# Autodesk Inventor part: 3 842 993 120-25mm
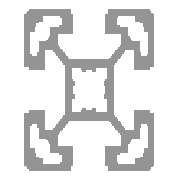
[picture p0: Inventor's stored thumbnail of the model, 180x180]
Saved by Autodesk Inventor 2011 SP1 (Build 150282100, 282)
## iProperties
Category: End -/-
Created: 2011-02
Part Number: 3 842 993 120-25mm
Document SubType Name: Modeling
Designer: SRW
Density: 2.71 g/cm^3
Categories: <MemberInstance><Categories><Category DisplayName="Structural Shapes" InternalName="089c4875-fa83-4c05-b084-43b9cc11f5ed" Mnemonic="GRDR"><CategoryParameter Dis
Stock Number: 3 842 993 120
Description: PROFILE 40x40, -/-
Material: Aluminum-6061
Mass: 37.6546 g
Surface Area: 139.763 cm^2
Volume: 13.8947 cm^3
G_L: 25.000 mm
Author: SRW
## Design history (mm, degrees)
node "Blocks"
  sketch "40x40"
    geometry: L1 (43.982, 25.257)-(43.982, 22.155); L2 (43.982, 22.155)-(47.084, 22.155); L3 (47.084, 22.155)-(47.484, 23.071); L4 (51.48, 23.071)-(51.88, 22.155); L5 (51.88, 22.155)-(54.982, 22.155); L6 (54.982, 22.155)-(54.982, 25.257); L7 (54.982, 25.257)-(54.065, 25.656); L8 (54.065, 29.653)-(54.982, 30.053); L9 (54.982, 30.053)-(54.982, 33.155); L10 (54.982, 33.155)-(51.88, 33.155); L11 (51.88, 33.155)-(51.48, 32.238); L12 (47.484, 32.238)-(47.084, 33.155); L13 (67.982, 42.155)-(66.732, 42.155); L14 (63.982, 44.905)-(63.982, 46.155); L15 (63.982, 46.155)-(58.982, 46.155); L16 (58.982, 43.155)-(61.232, 43.155); L17 (61.232, 43.155)-(61.232, 42.155); L18 (63.982, 39.405)-(64.982, 39.405); L19 (64.982, 39.405)-(64.982, 37.155); L20 (67.982, 37.155)-(67.982, 42.155); L21 (54.482, 9.155)-(55.282, 9.155); L22 (54.482, 13.655)-(54.482, 9.155); L23 (59.532, 13.655)-(54.482, 13.655); L24 (59.532, 16.191)-(59.532, 13.655); L25 (55.568, 20.155)-(59.532, 16.191); L26 (43.396, 20.155)-(55.568, 20.155); L27 (39.432, 16.191)-(43.396, 20.155); L28 (39.432, 13.655)-(39.432, 16.191); L29 (44.482, 13.655)-(39.432, 13.655); L30 (44.482, 9.155)-(44.482, 13.655); L31 (43.682, 9.155)-(44.482, 9.155); L32 (43.682, 7.655)-(43.682, 9.155); L33 (32.482, 7.655)-(43.682, 7.655); L34 (29.482, 21.855)-(29.482, 10.655); L35 (30.982, 21.855)-(29.482, 21.855); L36 (30.982, 22.655)-(30.982, 21.855); L37 (35.482, 22.655)-(30.982, 22.655); L38 (35.482, 17.605)-(35.482, 22.655); L39 (38.018, 17.605)-(35.482, 17.605); L40 (41.982, 21.569)-(38.018, 17.605); L41 (41.982, 33.741)-(41.982, 21.569); L42 (38.018, 37.705)-(41.982, 33.741); L43 (35.482, 37.705)-(38.018, 37.705); L44 (35.482, 32.655)-(35.482, 37.705); L45 (30.982, 32.655)-(35.482, 32.655); L46 (30.982, 33.455)-(30.982, 32.655); L47 (29.482, 33.455)-(30.982, 33.455); L48 (29.482, 44.655)-(29.482, 33.455); L49 (43.682, 47.655)-(32.482, 47.655); L50 (43.682, 46.155)-(43.682, 47.655); L51 (44.482, 46.155)-(43.682, 46.155); L52 (44.482, 41.655)-(44.482, 46.155); L53 (39.432, 41.655)-(44.482, 41.655); L54 (39.432, 39.119)-(39.432, 41.655); L55 (43.396, 35.155)-(39.432, 39.119); L56 (55.568, 35.155)-(43.396, 35.155); L57 (59.532, 39.119)-(55.568, 35.155); L58 (59.532, 41.655)-(59.532, 39.119); L59 (54.482, 41.655)-(59.532, 41.655); L60 (54.482, 46.155)-(54.482, 41.655); L61 (55.282, 46.155)-(54.482, 46.155); L62 (55.282, 47.655)-(55.282, 46.155); L63 (66.482, 47.655)-(55.282, 47.655); L64 (69.482, 33.455)-(69.482, 44.655)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; A1 r 5 centre (49.482, 27.655) between (47.484, 23.071) and (51.48, 23.071); A2 r 5 centre (49.482, 27.655) between (54.065, 25.656) and (54.065, 29.653); A3 r 5 centre (49.482, 27.655) between (51.48, 32.238) and (47.484, 32.238); A4 r 2.75 centre (63.982, 42.155) between (66.732, 42.155) and (63.982, 44.905); A5 r 1.5 centre (58.982, 44.655) between (58.982, 46.155) and (58.982, 43.155); A6 r 2.75 centre (63.982, 42.155) between (61.232, 42.155) and (63.982, 39.405); A7 r 1.5 centre (66.482, 37.155) between (64.982, 37.155) and (67.982, 37.155); A8 r 3 centre (32.482, 10.655) between (29.482, 10.655) and (32.482, 7.655); A9 r 3 centre (32.482, 44.655) between (32.482, 47.655) and (29.482, 44.655); A10 r 3 centre (66.482, 44.655) between (69.482, 44.655) and (66.482, 47.655); A11 r 3 centre (66.482, 10.655) between (66.482, 7.655) and (69.482, 10.655); A12 r 1.5 centre (58.982, 10.655) between (58.982, 12.155) and (58.982, 9.155); A13 r 2.75 centre (63.982, 13.155) between (63.982, 10.405) and (66.732, 13.155); A14 r 1.5 centre (66.482, 18.155) between (67.982, 18.155) and (64.982, 18.155); A15 r 2.75 centre (63.982, 13.155) between (63.982, 15.905) and (61.232, 13.155); A16 r 2.75 centre (34.982, 13.155) between (32.232, 13.155) and (34.982, 10.405); A17 r 1.5 centre (39.982, 10.655) between (39.982, 9.155) and (39.982, 12.155); A18 r 2.75 centre (34.982, 13.155) between (37.732, 13.155) and (34.982, 15.905); A19 r 1.5 centre (32.482, 18.155) between (33.982, 18.155) and (30.982, 18.155); A20 r 1.5 centre (39.982, 44.655) between (39.982, 43.155) and (39.982, 46.155); A21 r 2.75 centre (34.982, 42.155) between (34.982, 44.905) and (32.232, 42.155); A22 r 1.5 centre (32.482, 37.155) between (30.982, 37.155) and (33.982, 37.155); A23 r 2.75 centre (34.982, 42.155) between (34.982, 39.405) and (37.732, 42.155); A24 r 5 centre (49.482, 27.655) between (44.899, 29.653) and (44.899, 25.656); 1 further point
    constraints: 216 end point, 48 point on circle, 24 centre point, 1 coincident
node "Start Plane"
node "End Plane"
sketch "Sketch1"
  geometry: 1 further point
  constraints: 1 other
extrude "Body" new body sketch "Sketch1" stored distance "d4" = 0.13; taper "d5" = 0 deg
node "Driven Length"
  sketch "Sketch47"
    geometry: L1 (0, 0)-(10, 0) reference
    constraints: 2 end point, 1 horizontal
  workplane "Work Plane20"
  sketch "Sketch48"
    geometry: L1 (-28, 0)-(28, 0) reference; L2 (-28, 25)-(28, 25) reference
    dimensions: "d7" = 25 distance between parallel lines of L1 L2 (derived)
sketch "Sketch9"
  geometry: 1 further point
hole "M12/-" sketch "Sketch9" at (0, 0) diameter "d17" = 10.106; stored, may be unused: countersink angle "d21" = 90 deg, drill point angle "d23" = 118 deg; dims "d18" = 6, "d19" = 4, "d20" = 2, "d22" = 55
sketch "Sketch10"
  geometry: 1 further point
hole "-/M12" sketch "Sketch10" at (0, 0) diameter "d24" = 10.106; stored, may be unused: countersink angle "d28" = 90 deg, drill point angle "d30" = 118 deg; dims "d25" = 6, "d26" = 4, "d27" = 2, "d29" = 55
sketch "Sketch11"
  geometry: L1 (-13.7, 0)-(12.2, 0) reference; C1 r 8.5 at (0, 20); 1 further point
  constraints: 1 centre point, 1 vertical alignment
  dimensions: "d31" = 20 distance from line of C1.centre L1; "d32" = 17 diameter of C1
extrude "D17/-" cut sketch "Sketch11" stored distance "d33" = 10; taper "d34" = 0 deg
sketch "Sketch12"
  geometry: L1 (-13.7, 25)-(12.2, 25) reference; C1 r 8.5 at (0, 5); 1 further point
  constraints: 1 centre point, 1 vertical alignment
  dimensions: "d35" = 17 diameter of C1; "d36" = 20 distance from line of L1 C1.centre
extrude "-/D17" cut sketch "Sketch12" stored distance "d37" = 10; taper "d38" = 0 deg
sketch "Sketch13"
  geometry: L1 (-12.98, 0)-(7.88, 0) reference; C1 r 4.9 at (0, 20); 1 further point
  constraints: 1 centre point, 1 vertical alignment
  dimensions: "d39" = 9.8 diameter of C1; "d40" = 20 distance from line of C1.centre L1
extrude "D9.8/-" cut sketch "Sketch13" stored distance "d41" = 10; taper "d42" = 0 deg
sketch "Sketch14"
  geometry: L1 (-12.98, 25)-(7.88, 25) reference; C1 r 4.9 at (0, 5); 1 further point
  constraints: 1 centre point, 1 vertical alignment
  dimensions: "d43" = 9.8 diameter of C1; "d44" = 20 distance from line of L1 C1.centre
extrude "-/D9.8" cut sketch "Sketch14" stored distance "d45" = 10; taper "d46" = 0 deg
sketch "Sketch15"
  geometry: L1 (-6.86, 25)-(6.86, 25) reference; C1 r 4.9 at (0, 5); 1 further point
  constraints: 1 centre point, 1 vertical alignment
  dimensions: "d47" = 9.8 diameter of C1; "d48" = 20 distance from line of L1 C1.centre
extrude "-/D9.8VS" cut sketch "Sketch15" stored distance "d49" = 10; taper "d50" = 0 deg
sketch "Sketch26"
  geometry: L1 (-6.86, 0)-(6.86, 0) reference; C1 r 4.9 at (0, 20); 1 further point
  constraints: 1 centre point, 1 vertical alignment
  dimensions: "d62" = 9.8 diameter of C1; "d65" = 20 distance from line of L1 C1.centre
extrude "D9.8VS/-" cut sketch "Sketch26" stored distance "d63" = 10; taper "d64" = 0 deg
sketch "Sketch37"
  geometry: L1 (-11.9, 0)-(11.9, 0) reference; L2 (-11.9, 25)-(11.9, 25) reference; C1 r 8.5 at (0, 20); 1 further point
  constraints: 1 centre point, 1 vertical alignment
  dimensions: "d76" = 20 distance from line of C1.centre L1; "d77" = 17 diameter of C1
extrude "D17VS/-" cut sketch "Sketch37" stored distance "d78" = 10; taper "d79" = 0 deg
sketch "Sketch38"
  geometry: L1 (-11.9, 25)-(11.9, 25) reference; C1 r 8.5 at (0, 5); 1 further point
  constraints: 1 centre point, 1 vertical alignment
  dimensions: "d80" = 17 diameter of C1; "d81" = 20 distance from line of L1 C1.centre
extrude "-/D17VS" cut sketch "Sketch38" stored distance "d82" = 10; taper "d83" = 0 deg
body "Solid1"
node "40x40:1"
other parameters: "Length" = 25, "G_OFFSET_START" = 0 [user parameter; used in 2 equation terms], "G_OFFSET_END" = 0 [user parameter; used in 2 equation terms], "d2" = 0 (computed from G_OFFSET_START), "d3" = 25 (= Length + G_OFFSET_END), "G_L" = 25 (= d7) [user parameter], "Length2" = 25 (= G_OFFSET_START + Length + G_OFFSET_END) [user parameter], "d92" = 90 deg
